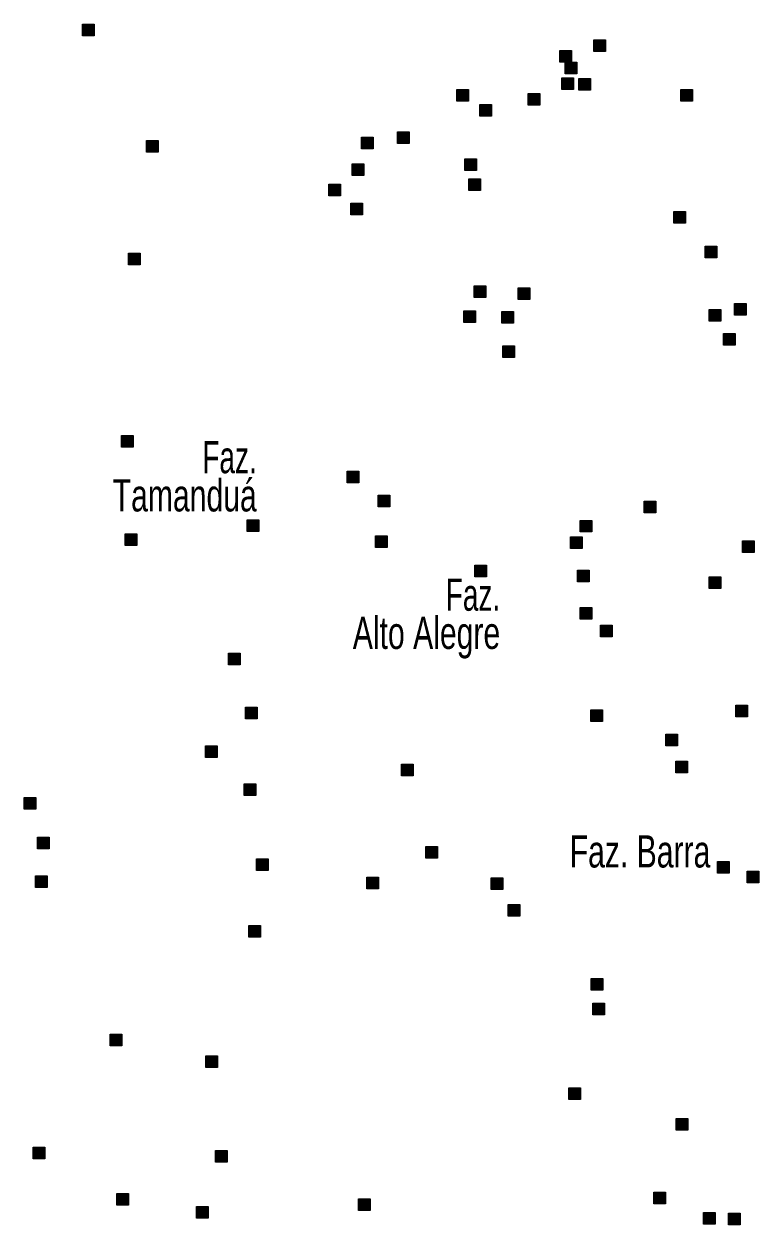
# Model space of a CAD drawing. Extents: x 445.6 to 500, y 8618.1 to 8673.4.
# Drawn here: x 457.93 to 461.58, y 8644.62 to 8650.59 of the extents above; entities that cross this region are included whole.
import ezdxf
from ezdxf.enums import TextEntityAlignment as Align

# ---------------------------------------------------------------- set-up
doc = ezdxf.new("R2010")
doc.units = 0
doc.header["$LTSCALE"] = 0.064
doc.layers.add('2', color=7, linetype='Continuous', lineweight=25)
doc.layers.add('61', color=7, linetype='Continuous')

msp = doc.modelspace()

# ---------------------------------------------------------------- hatches: boundary and pattern name
at = {"layer": '2'}
for points in [[(458.2179, 8650.5901), (458.2759, 8650.5901), (458.2759, 8650.5321), (458.2179, 8650.5321)], [(460.7583, 8650.5122), (460.8163, 8650.5122), (460.8163, 8650.4542), (460.7583, 8650.4542)], [(460.5895, 8650.458), (460.6475, 8650.458), (460.6475, 8650.4), (460.5895, 8650.4)], [(460.6165, 8650.4004), (460.6745, 8650.4004), (460.6745, 8650.3424), (460.6165, 8650.3424)], [(460.5996, 8650.3225), (460.6576, 8650.3225), (460.6576, 8650.2645), (460.5996, 8650.2645)], [(460.684, 8650.3191), (460.742, 8650.3191), (460.742, 8650.2611), (460.684, 8650.2611)], [(460.0776, 8650.2649), (460.1356, 8650.2649), (460.1356, 8650.2069), (460.0776, 8650.2069)], [(461.1907, 8650.2649), (461.2487, 8650.2649), (461.2487, 8650.2069), (461.1907, 8650.2069)], [(460.1925, 8650.1903), (460.2505, 8650.1903), (460.2505, 8650.1323), (460.1925, 8650.1323)], [(460.4323, 8650.2445), (460.4903, 8650.2445), (460.4903, 8650.1865), (460.4323, 8650.1865)], [(458.5346, 8650.0106), (458.5926, 8650.0106), (458.5926, 8649.9526), (458.5346, 8649.9526)], [(459.6042, 8650.0276), (459.6622, 8650.0276), (459.6622, 8649.9696), (459.6042, 8649.9696)], [(459.7832, 8650.0547), (459.8412, 8650.0547), (459.8412, 8649.9967), (459.7832, 8649.9967)], [(459.5569, 8649.8954), (459.6149, 8649.8954), (459.6149, 8649.8374), (459.5569, 8649.8374)], [(460.1176, 8649.9191), (460.1756, 8649.9191), (460.1756, 8649.8611), (460.1176, 8649.8611)], [(459.4421, 8649.7938), (459.5001, 8649.7938), (459.5001, 8649.7358), (459.4421, 8649.7358)], [(460.1379, 8649.8209), (460.1959, 8649.8209), (460.1959, 8649.7629), (460.1379, 8649.7629)], [(459.5501, 8649.6989), (459.6081, 8649.6989), (459.6081, 8649.6409), (459.5501, 8649.6409)], [(461.1558, 8649.6576), (461.2138, 8649.6576), (461.2138, 8649.5996), (461.1558, 8649.5996)], [(461.3119, 8649.4856), (461.3699, 8649.4856), (461.3699, 8649.4276), (461.3119, 8649.4276)], [(458.4456, 8649.4516), (458.5036, 8649.4516), (458.5036, 8649.3936), (458.4456, 8649.3936)], [(460.1634, 8649.2891), (460.2214, 8649.2891), (460.2214, 8649.2311), (460.1634, 8649.2311)], [(460.383, 8649.2789), (460.441, 8649.2789), (460.441, 8649.2209), (460.383, 8649.2209)], [(461.4571, 8649.201), (461.5151, 8649.201), (461.5151, 8649.143), (461.4571, 8649.143)], [(460.1127, 8649.1637), (460.1707, 8649.1637), (460.1707, 8649.1057), (460.1127, 8649.1057)], [(460.3019, 8649.1603), (460.3599, 8649.1603), (460.3599, 8649.1023), (460.3019, 8649.1023)], [(461.3321, 8649.1705), (461.3901, 8649.1705), (461.3901, 8649.1125), (461.3321, 8649.1125)], [(461.4031, 8649.0519), (461.4611, 8649.0519), (461.4611, 8648.9939), (461.4031, 8648.9939)], [(460.3068, 8648.9908), (460.3648, 8648.9908), (460.3648, 8648.9328), (460.3068, 8648.9328)], [(458.4118, 8648.5436), (458.4698, 8648.5436), (458.4698, 8648.4856), (458.4118, 8648.4856)], [(459.532, 8648.3664), (459.59, 8648.3664), (459.59, 8648.3084), (459.532, 8648.3084)], [(459.6863, 8648.2482), (459.7443, 8648.2482), (459.7443, 8648.1902), (459.6863, 8648.1902)], [(461.0081, 8648.2173), (461.0661, 8648.2173), (461.0661, 8648.1593), (461.0081, 8648.1593)], [(459.0354, 8648.1258), (459.0934, 8648.1258), (459.0934, 8648.0678), (459.0354, 8648.0678)], [(460.6906, 8648.1225), (460.7486, 8648.1225), (460.7486, 8648.0645), (460.6906, 8648.0645)], [(458.4298, 8648.0551), (458.4878, 8648.0551), (458.4878, 8647.9971), (458.4298, 8647.9971)], [(459.6727, 8648.0447), (459.7307, 8648.0447), (459.7307, 8647.9867), (459.6727, 8647.9867)], [(460.6433, 8648.0411), (460.7013, 8648.0411), (460.7013, 8647.9831), (460.6433, 8647.9831)], [(461.4973, 8648.0214), (461.5553, 8648.0214), (461.5553, 8647.9634), (461.4973, 8647.9634)], [(460.1673, 8647.8997), (460.2253, 8647.8997), (460.2253, 8647.8417), (460.1673, 8647.8417)], [(460.6771, 8647.8751), (460.7351, 8647.8751), (460.7351, 8647.8171), (460.6771, 8647.8171)], [(461.332, 8647.8418), (461.39, 8647.8418), (461.39, 8647.7838), (461.332, 8647.7838)], [(460.6908, 8647.6896), (460.7488, 8647.6896), (460.7488, 8647.6316), (460.6908, 8647.6316)], [(460.7922, 8647.6015), (460.8502, 8647.6015), (460.8502, 8647.5435), (460.7922, 8647.5435)], [(458.9433, 8647.4622), (459.0013, 8647.4622), (459.0013, 8647.4042), (458.9433, 8647.4042)], [(461.4641, 8647.2043), (461.5221, 8647.2043), (461.5221, 8647.1463), (461.4641, 8647.1463)], [(459.0268, 8647.1938), (459.0848, 8647.1938), (459.0848, 8647.1358), (459.0268, 8647.1358)], [(460.7431, 8647.1803), (460.8011, 8647.1803), (460.8011, 8647.1223), (460.7431, 8647.1223)], [(461.1162, 8647.0586), (461.1742, 8647.0586), (461.1742, 8647.0006), (461.1162, 8647.0006)], [(458.8284, 8647.0014), (458.8864, 8647.0014), (458.8864, 8646.9434), (458.8284, 8646.9434)], [(459.8025, 8646.9104), (459.8605, 8646.9104), (459.8605, 8646.8524), (459.8025, 8646.8524)], [(461.1659, 8646.9259), (461.2239, 8646.9259), (461.2239, 8646.8679), (461.1659, 8646.8679)], [(459.021, 8646.8117), (459.079, 8646.8117), (459.079, 8646.7537), (459.021, 8646.7537)], [(457.9265, 8646.7439), (457.9845, 8646.7439), (457.9845, 8646.6859), (457.9265, 8646.6859)], [(457.9941, 8646.5474), (458.0521, 8646.5474), (458.0521, 8646.4894), (457.9941, 8646.4894)], [(459.9241, 8646.5004), (459.9821, 8646.5004), (459.9821, 8646.4424), (459.9241, 8646.4424)], [(459.0818, 8646.439), (459.1398, 8646.439), (459.1398, 8646.381), (459.0818, 8646.381)], [(461.3729, 8646.4257), (461.4309, 8646.4257), (461.4309, 8646.3677), (461.3729, 8646.3677)], [(461.5215, 8646.3783), (461.5795, 8646.3783), (461.5795, 8646.3203), (461.5215, 8646.3203)], [(457.984, 8646.3543), (458.042, 8646.3543), (458.042, 8646.2963), (457.984, 8646.2963)], [(459.6302, 8646.348), (459.6882, 8646.348), (459.6882, 8646.29), (459.6302, 8646.29)], [(460.2483, 8646.3446), (460.3063, 8646.3446), (460.3063, 8646.2866), (460.2483, 8646.2866)], [(460.3328, 8646.2124), (460.3908, 8646.2124), (460.3908, 8646.1544), (460.3328, 8646.1544)], [(459.0446, 8646.1079), (459.1026, 8646.1079), (459.1026, 8646.0499), (459.0446, 8646.0499)], [(460.7461, 8645.844), (460.8041, 8645.844), (460.8041, 8645.786), (460.7461, 8645.786)], [(460.7529, 8645.7219), (460.8109, 8645.7219), (460.8109, 8645.6639), (460.7529, 8645.6639)], [(458.3544, 8645.5682), (458.4124, 8645.5682), (458.4124, 8645.5102), (458.3544, 8645.5102)], [(458.8306, 8645.4598), (458.8886, 8645.4598), (458.8886, 8645.4018), (458.8306, 8645.4018)], [(460.6344, 8645.3005), (460.6924, 8645.3005), (460.6924, 8645.2425), (460.6344, 8645.2425)], [(461.1681, 8645.1481), (461.2261, 8645.1481), (461.2261, 8645.0901), (461.1681, 8645.0901)], [(457.9727, 8645.0058), (458.0307, 8645.0058), (458.0307, 8644.9478), (457.9727, 8644.9478)], [(458.8779, 8644.9889), (458.9359, 8644.9889), (458.9359, 8644.9309), (458.8779, 8644.9309)], [(458.3881, 8644.7754), (458.4461, 8644.7754), (458.4461, 8644.7174), (458.3881, 8644.7174)], [(461.0566, 8644.7822), (461.1146, 8644.7822), (461.1146, 8644.7242), (461.0566, 8644.7242)], [(458.7834, 8644.711), (458.8414, 8644.711), (458.8414, 8644.653), (458.7834, 8644.653)], [(459.5891, 8644.7483), (459.6471, 8644.7483), (459.6471, 8644.6903), (459.5891, 8644.6903)], [(461.3032, 8644.6805), (461.3612, 8644.6805), (461.3612, 8644.6225), (461.3032, 8644.6225)], [(461.4282, 8644.6771), (461.4862, 8644.6771), (461.4862, 8644.6191), (461.4282, 8644.6191)]]:
    msp.add_hatch(color=256, dxfattribs=at).paths.add_polyline_path(points)

# ---------------------------------------------------------------- linework, layer by layer
for points in [[(458.2179, 8650.5901), (458.2759, 8650.5901), (458.2759, 8650.5321), (458.2179, 8650.5321)], [(460.7583, 8650.5122), (460.8163, 8650.5122), (460.8163, 8650.4542), (460.7583, 8650.4542)], [(460.5895, 8650.458), (460.6475, 8650.458), (460.6475, 8650.4), (460.5895, 8650.4)], [(460.6165, 8650.4004), (460.6745, 8650.4004), (460.6745, 8650.3424), (460.6165, 8650.3424)], [(460.5996, 8650.3225), (460.6576, 8650.3225), (460.6576, 8650.2645), (460.5996, 8650.2645)], [(460.684, 8650.3191), (460.742, 8650.3191), (460.742, 8650.2611), (460.684, 8650.2611)], [(460.0776, 8650.2649), (460.1356, 8650.2649), (460.1356, 8650.2069), (460.0776, 8650.2069)], [(461.1907, 8650.2649), (461.2487, 8650.2649), (461.2487, 8650.2069), (461.1907, 8650.2069)], [(460.1925, 8650.1903), (460.2505, 8650.1903), (460.2505, 8650.1323), (460.1925, 8650.1323)], [(460.4323, 8650.2445), (460.4903, 8650.2445), (460.4903, 8650.1865), (460.4323, 8650.1865)], [(458.5346, 8650.0106), (458.5926, 8650.0106), (458.5926, 8649.9526), (458.5346, 8649.9526)], [(459.6042, 8650.0276), (459.6622, 8650.0276), (459.6622, 8649.9696), (459.6042, 8649.9696)], [(459.7832, 8650.0547), (459.8412, 8650.0547), (459.8412, 8649.9967), (459.7832, 8649.9967)], [(459.5569, 8649.8954), (459.6149, 8649.8954), (459.6149, 8649.8374), (459.5569, 8649.8374)], [(460.1176, 8649.9191), (460.1756, 8649.9191), (460.1756, 8649.8611), (460.1176, 8649.8611)], [(459.4421, 8649.7938), (459.5001, 8649.7938), (459.5001, 8649.7358), (459.4421, 8649.7358)], [(460.1379, 8649.8209), (460.1959, 8649.8209), (460.1959, 8649.7629), (460.1379, 8649.7629)], [(459.5501, 8649.6989), (459.6081, 8649.6989), (459.6081, 8649.6409), (459.5501, 8649.6409)], [(461.1558, 8649.6576), (461.2138, 8649.6576), (461.2138, 8649.5996), (461.1558, 8649.5996)], [(461.3119, 8649.4856), (461.3699, 8649.4856), (461.3699, 8649.4276), (461.3119, 8649.4276)], [(458.4456, 8649.4516), (458.5036, 8649.4516), (458.5036, 8649.3936), (458.4456, 8649.3936)], [(460.1634, 8649.2891), (460.2214, 8649.2891), (460.2214, 8649.2311), (460.1634, 8649.2311)], [(460.383, 8649.2789), (460.441, 8649.2789), (460.441, 8649.2209), (460.383, 8649.2209)], [(461.4571, 8649.201), (461.5151, 8649.201), (461.5151, 8649.143), (461.4571, 8649.143)], [(460.1127, 8649.1637), (460.1707, 8649.1637), (460.1707, 8649.1057), (460.1127, 8649.1057)], [(460.3019, 8649.1603), (460.3599, 8649.1603), (460.3599, 8649.1023), (460.3019, 8649.1023)], [(461.3321, 8649.1705), (461.3901, 8649.1705), (461.3901, 8649.1125), (461.3321, 8649.1125)], [(461.4031, 8649.0519), (461.4611, 8649.0519), (461.4611, 8648.9939), (461.4031, 8648.9939)], [(460.3068, 8648.9908), (460.3648, 8648.9908), (460.3648, 8648.9328), (460.3068, 8648.9328)], [(458.4118, 8648.5436), (458.4698, 8648.5436), (458.4698, 8648.4856), (458.4118, 8648.4856)], [(459.532, 8648.3664), (459.59, 8648.3664), (459.59, 8648.3084), (459.532, 8648.3084)], [(459.6863, 8648.2482), (459.7443, 8648.2482), (459.7443, 8648.1902), (459.6863, 8648.1902)], [(461.0081, 8648.2173), (461.0661, 8648.2173), (461.0661, 8648.1593), (461.0081, 8648.1593)], [(459.0354, 8648.1258), (459.0934, 8648.1258), (459.0934, 8648.0678), (459.0354, 8648.0678)], [(460.6906, 8648.1225), (460.7486, 8648.1225), (460.7486, 8648.0645), (460.6906, 8648.0645)], [(458.4298, 8648.0551), (458.4878, 8648.0551), (458.4878, 8647.9971), (458.4298, 8647.9971)], [(459.6727, 8648.0447), (459.7307, 8648.0447), (459.7307, 8647.9867), (459.6727, 8647.9867)], [(460.6433, 8648.0411), (460.7013, 8648.0411), (460.7013, 8647.9831), (460.6433, 8647.9831)], [(461.4973, 8648.0214), (461.5553, 8648.0214), (461.5553, 8647.9634), (461.4973, 8647.9634)], [(460.1673, 8647.8997), (460.2253, 8647.8997), (460.2253, 8647.8417), (460.1673, 8647.8417)], [(460.6771, 8647.8751), (460.7351, 8647.8751), (460.7351, 8647.8171), (460.6771, 8647.8171)], [(461.332, 8647.8418), (461.39, 8647.8418), (461.39, 8647.7838), (461.332, 8647.7838)], [(460.6908, 8647.6896), (460.7488, 8647.6896), (460.7488, 8647.6316), (460.6908, 8647.6316)], [(460.7922, 8647.6015), (460.8502, 8647.6015), (460.8502, 8647.5435), (460.7922, 8647.5435)], [(458.9433, 8647.4622), (459.0013, 8647.4622), (459.0013, 8647.4042), (458.9433, 8647.4042)], [(461.4641, 8647.2043), (461.5221, 8647.2043), (461.5221, 8647.1463), (461.4641, 8647.1463)], [(459.0268, 8647.1938), (459.0848, 8647.1938), (459.0848, 8647.1358), (459.0268, 8647.1358)], [(460.7431, 8647.1803), (460.8011, 8647.1803), (460.8011, 8647.1223), (460.7431, 8647.1223)], [(461.1162, 8647.0586), (461.1742, 8647.0586), (461.1742, 8647.0006), (461.1162, 8647.0006)], [(458.8284, 8647.0014), (458.8864, 8647.0014), (458.8864, 8646.9434), (458.8284, 8646.9434)], [(459.8025, 8646.9104), (459.8605, 8646.9104), (459.8605, 8646.8524), (459.8025, 8646.8524)], [(461.1659, 8646.9259), (461.2239, 8646.9259), (461.2239, 8646.8679), (461.1659, 8646.8679)], [(459.021, 8646.8117), (459.079, 8646.8117), (459.079, 8646.7537), (459.021, 8646.7537)], [(457.9265, 8646.7439), (457.9845, 8646.7439), (457.9845, 8646.6859), (457.9265, 8646.6859)], [(457.9941, 8646.5474), (458.0521, 8646.5474), (458.0521, 8646.4894), (457.9941, 8646.4894)], [(459.9241, 8646.5004), (459.9821, 8646.5004), (459.9821, 8646.4424), (459.9241, 8646.4424)], [(459.0818, 8646.439), (459.1398, 8646.439), (459.1398, 8646.381), (459.0818, 8646.381)], [(461.3729, 8646.4257), (461.4309, 8646.4257), (461.4309, 8646.3677), (461.3729, 8646.3677)], [(461.5215, 8646.3783), (461.5795, 8646.3783), (461.5795, 8646.3203), (461.5215, 8646.3203)], [(457.984, 8646.3543), (458.042, 8646.3543), (458.042, 8646.2963), (457.984, 8646.2963)], [(459.6302, 8646.348), (459.6882, 8646.348), (459.6882, 8646.29), (459.6302, 8646.29)], [(460.2483, 8646.3446), (460.3063, 8646.3446), (460.3063, 8646.2866), (460.2483, 8646.2866)], [(460.3328, 8646.2124), (460.3908, 8646.2124), (460.3908, 8646.1544), (460.3328, 8646.1544)], [(459.0446, 8646.1079), (459.1026, 8646.1079), (459.1026, 8646.0499), (459.0446, 8646.0499)], [(460.7461, 8645.844), (460.8041, 8645.844), (460.8041, 8645.786), (460.7461, 8645.786)], [(460.7529, 8645.7219), (460.8109, 8645.7219), (460.8109, 8645.6639), (460.7529, 8645.6639)], [(458.3544, 8645.5682), (458.4124, 8645.5682), (458.4124, 8645.5102), (458.3544, 8645.5102)], [(458.8306, 8645.4598), (458.8886, 8645.4598), (458.8886, 8645.4018), (458.8306, 8645.4018)], [(460.6344, 8645.3005), (460.6924, 8645.3005), (460.6924, 8645.2425), (460.6344, 8645.2425)], [(461.1681, 8645.1481), (461.2261, 8645.1481), (461.2261, 8645.0901), (461.1681, 8645.0901)], [(457.9727, 8645.0058), (458.0307, 8645.0058), (458.0307, 8644.9478), (457.9727, 8644.9478)], [(458.8779, 8644.9889), (458.9359, 8644.9889), (458.9359, 8644.9309), (458.8779, 8644.9309)], [(458.3881, 8644.7754), (458.4461, 8644.7754), (458.4461, 8644.7174), (458.3881, 8644.7174)], [(461.0566, 8644.7822), (461.1146, 8644.7822), (461.1146, 8644.7242), (461.0566, 8644.7242)], [(458.7834, 8644.711), (458.8414, 8644.711), (458.8414, 8644.653), (458.7834, 8644.653)], [(459.5891, 8644.7483), (459.6471, 8644.7483), (459.6471, 8644.6903), (459.5891, 8644.6903)], [(461.3032, 8644.6805), (461.3612, 8644.6805), (461.3612, 8644.6225), (461.3032, 8644.6225)], [(461.4282, 8644.6771), (461.4862, 8644.6771), (461.4862, 8644.6191), (461.4282, 8644.6191)]]:
    msp.add_lwpolyline(points, close=True, dxfattribs=at)

# ---------------------------------------------------------------- texts
at = {"layer": '61'}
for s, width, p in [('Faz.', 0.65, (459.0832, 8648.3568)), ('Tamanduá', 0.7, (459.0832, 8648.1668)), ('Faz.', 0.65, (460.2933, 8647.6731)), ('Alto Alegre', 0.7, (460.2933, 8647.4831))]:
    msp.add_text(s, height=0.16, dxfattribs=dict(at, width=width)).set_placement(p, align=Align.RIGHT)
at = {"layer": '61', "width": 0.7}
msp.add_text('Faz. Barra', height=0.16, dxfattribs=at).set_placement((460.6387, 8646.3965))

doc.saveas('drawing.dxf')
